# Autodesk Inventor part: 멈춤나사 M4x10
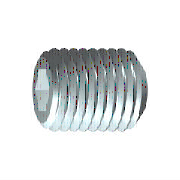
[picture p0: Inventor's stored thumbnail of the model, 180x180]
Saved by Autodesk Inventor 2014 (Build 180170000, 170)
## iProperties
Created: 2012-02
Part Number: 멈춤나사 M4x10
Material: 강철, 연강
Description: 6각 소켓 머리 없는 멈춤 나사
Document SubType Name: Modeling
Standard: KS B 1028
Designer: mduedu
Standards Organization: KS
Language: ko-KR
Size Designation: 납작점M4x10
Categories: <MemberInstance><Categories><Category DisplayName="조임쇠" InternalName="e4da775c-781d-43d5-af7c-5136215cf5a6" Mnemonic="FSTN"><Category DisplayName="볼트" InternalN
Density: 1 g/cm^3
Appearance: Steel
IsCustomPart: 1
Author: mduedu
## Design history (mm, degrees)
sketch "스케치1"
  geometry: L1 (0, 0)-(6.833, 0); L2 (10, 1.155)-(10, 2); L3 (10, 2)-(0, 2); L4 (10, 1.155)-(7.5, 1.155); L5 (7.5, 1.155)-(6.833, 0); L6 (0, -0.4)-(0, 2.4) reference; L7 (0, 2)-(0, 0)
  constraints: 13 end point, 3 parallel, 1 collinear, 1 perpendicular, 1 point on line
  dimensions: "d0" = 2.5 distance of L2.start L4.end (= INTI); "d1" = 60 deg angle of L5 L1; "d2" = 4 diameter of L3 L1 (= NND); "d3" = 2.3094 diameter of L4 L1 (= 1.1547 x SW); "d5" = 10 distance from line of L2 L3.end (= NLG)
revolve "본체" sketch "스케치1" stored, may be unused: angle "d6" = 90 deg
sketch "스케치2"
  geometry: L1 (-0.577, 1)-(0.577, 1); L2 (0.577, 1)-(1.155, 0); L3 (1.155, 0)-(0.577, -1); L4 (0.577, -1)-(-0.577, -1); L5 (-0.577, -1)-(-1.155, 0); L6 (-1.155, 0)-(-0.577, 1); A1 r 1.155 centre (0, 0) between (-0.577, 1) and (0.577, 1) reference; 2 further points
  constraints: 12 end point, 2 point on circle, 1 coincident, 1 horizontal, 11 other
extrude "슬롯" join sketch "스케치2" taper "d9" = 0 deg; stored distance "d21" = 10
workaxis "Work Axis1"
workplane "Work Plane1"
workaxis "Work Axis3"
sketch "Sketch4"
  geometry: L1 (0, 1.571)-(-0.429, 2) reference; L2 (0, 1.571)-(1.571, 0); 1 further point
  constraints: 2 end point, 1 collinear
workpoint "Work Point1"
body "Solid1"
chamfer "모따기1" distance "d7" = 0.42941 (= -0.5 x GD1 + 0.5 x NND); stored, may be unused: angle "d8" = 45 deg (= FAWI), second distance "d29" = 0.42941 (= -0.5 x GD1 + 0.5 x NND)
feature "스레드" dims "d11" = 10 (= NLG), "d12" = 0
chamfer "모따기2" distance "d13" = 0.42941 (= -0.5 x GD1 + 0.5 x NND); stored, may be unused: angle "d14" = 45 deg (= FAWI), second distance "d30" = 0.42941 (= -0.5 x GD1 + 0.5 x NND)
other parameters: "NND" = 4 [user parameter; used in 5 equation terms], "NLG" = 10 [user parameter; used in 2 equation terms], "INTI" = 2.5 [user parameter; used in 1 equation term], "FAWI" = 45 deg [user parameter; used in 2 equation terms], "SW" = 2 [user parameter; used in 2 equation terms], "GD1" = 3.14117 (= THREADDIA - 1.2269 x PTC) [user parameter; used in 4 equation terms], "d4" = 0, "FAWI1" = 45 deg [user parameter], "d15" = 0, "d31" = 0, "GUL" = 0.42941 (= 0.61345 x PTC) [user parameter], "SPD" = 2.5 [user parameter], "TPU" = 14.28571 (computed from PTC) [user parameter], "TOA" = 30 deg [user parameter], "THREADDIA" = 4 [user parameter; used in 1 equation term], "PTC" = 0.7 [user parameter; used in 4 equation terms], "GAL" = 0.42941 (= 0.61345 x PTC) [user parameter], "E0" = 2.31 (= 1.155 x SW) [user parameter]
